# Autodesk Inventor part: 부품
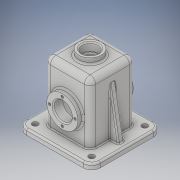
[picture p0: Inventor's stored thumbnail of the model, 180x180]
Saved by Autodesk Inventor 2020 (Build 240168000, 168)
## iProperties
Created: 2022-11
Part Number: 부품
Material: 일반
Document SubType Name: Modeling
Designer: com
Density: 1 g/cm^3
Appearance: 기본값
Author: com
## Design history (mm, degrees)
sketch "스케치1"
  geometry: L1 (65, -62)-(-65, -62); L2 (-65, -62)-(-65, 62); L3 (-65, 62)-(65, 62); L4 (65, 62)-(65, -62); L5 (65, -62)-(-65, 62); L6 (-65, -62)-(65, 62); 1 further point
  constraints: 12 end point, 2 midpoint, 2 parallel, 1 horizontal, 1 perpendicular
  dimensions: "d0" = 130 distance of L1.start L1.end; "d1" = 124 distance of L3.end L1.start
extrude "돌출1" new body sketch "스케치1" distance "d2" = 10; taper "d3" = 0 deg
fillet "모깎기1" dims "d4" = 15
fillet "모깎기2" dims "d5" = 3
sketch "스케치2"
  geometry: L1 (50, -59)-(-50, -59) reference; L2 (62, 47)-(62, -47) reference; L3 (-50, 59)-(50, 59) reference; L4 (-62, -47)-(-62, 47) reference; A1 r 12 centre (-50, -47) between (-62, -47) and (-50, -59) reference; A2 r 12 centre (50, -47) between (50, -59) and (62, -47) reference; A3 r 12 centre (50, 47) between (62, 47) and (50, 59) reference; A4 r 12 centre (-50, 47) between (-50, 59) and (-62, 47) reference; 5 further points
  constraints: 4 coincident
hole "구멍1" sketch "스케치2" at (-50, 47), (-50, -47), (50, -47), (50, 47) diameter "d6" = 10; stored, may be unused: countersink angle "d10" = 90 deg, drill point angle "d12" = 118 deg; dims "d7" = 6, "d8" = 8, "d9" = 4.4, "d11" = 8
sketch "스케치3"
  geometry: L1 (-40, 40)-(40, 40); L2 (40, 40)-(40, -40); L3 (40, -40)-(-40, -40); L4 (-40, -40)-(-40, 40); L5 (-40, 40)-(40, -40); L6 (40, 40)-(-40, -40); 1 further point
  constraints: 12 end point, 2 midpoint, 2 parallel, 1 horizontal, 1 perpendicular
  dimensions: "d13" = 80 distance of L1.start L1.end; "d25" = 80 distance of L1.end L2.end
extrude "돌출2" join sketch "스케치3" distance "d14" = 107; taper "d15" = 0 deg
fillet "모깎기3" dims "d16" = 10
sketch "스케치4"
  geometry: L1 (50, -62)-(-50, -62) reference; L2 (65, 47)-(65, -47) reference; L3 (-50, 62)-(50, 62) reference; L4 (-65, -47)-(-65, 47) reference; L5 (-32, 32)-(32, 32); L6 (32, 32)-(32, -32); L7 (32, -32)-(-32, -32); L8 (-32, -32)-(-32, 32); L9 (-32, 32)-(32, -32); L10 (32, 32)-(-32, -32); C1 r 5 at (50, 47) reference; C2 r 5 at (-50, -47) reference; C3 r 5 at (-50, 47) reference; C4 r 5 at (50, -47) reference; A1 r 15 centre (-50, -47) between (-65, -47) and (-50, -62) reference; A2 r 15 centre (50, -47) between (50, -62) and (65, -47) reference; A3 r 15 centre (50, 47) between (65, 47) and (50, 62) reference; A4 r 15 centre (-50, 47) between (-50, 62) and (-65, 47) reference; 1 further point
  constraints: 12 end point, 2 midpoint, 2 parallel, 1 horizontal, 1 perpendicular
  dimensions: "d17" = 64 distance of L5.start L5.end; "d18" = 64 distance between parallel lines of L5 L7
extrude "돌출3" cut sketch "스케치4" distance "d19" = 99; taper "d20" = 0 deg
sketch "스케치6"
  geometry: L1 (60, 97)-(60, 0) reference; L2 (0, 97)-(60, 97) reference; L3 (0, 0)-(0, 97) reference; L4 (60, 0)-(0, 0) reference; L5 (-20, -10)-(80, -10) reference; C1 r 16 at (30, 45); C2 r 27.5 at (30, 45); 1 further point
  constraints: 2 centre point, 1 coincident
  dimensions: "d30" = 55 distance from line of C1.centre L5; "d31" = 32 diameter of C1; "d32" = 55 diameter of C2
extrude "돌출6" join sketch "스케치6" distance "d33" = 9; taper "d34" = 0 deg
fillet "모깎기4" dims "d35" = 3
sketch "스케치7"
  geometry: L1 (0, 0)-(0, 97) reference; L2 (60, 0)-(0, 0) reference; L3 (60, 97)-(60, 0) reference; L4 (0, 97)-(60, 97) reference; L5 (-20, -10)-(80, -10) reference; C1 r 16 at (30, 45); C2 r 27.5 at (30, 45); 2 further points
  constraints: 2 centre point, 1 coincident, 1 midpoint, 1 vertical alignment
  dimensions: "d36" = 55 distance from line of L5 C1.centre; "d37" = 55 diameter of C2; "d38" = 32 diameter of C1
extrude "돌출7" join sketch "스케치7" distance "d39" = 9; taper "d40" = 0 deg
sketch "스케치8"
  geometry: C1 r 16 at (0, 0) reference; 1 further point
extrude "돌출8" cut sketch "스케치8" extent not by distance; stored distance "d41" = 9; taper "d42" = 0 deg
sketch "스케치9"
  geometry: C1 r 20 at (0, 0); C2 r 14 at (0, 0); 1 further point
  constraints: 2 centre point, 2 coincident
  dimensions: "d43" = 40 diameter of C1; "d44" = 28 diameter of C2
extrude "돌출9" join sketch "스케치9" distance "d45" = 10; taper "d46" = 0 deg
fillet "모깎기5" dims "d47" = 3
sketch "스케치10"
  geometry: C1 r 10.5 at (0, 0); C2 r 14 at (0, 0) reference; C3 r 14 at (0, 0); 1 further point
  constraints: 2 centre point, 2 coincident, 1 concentric
  dimensions: "d48" = 21 diameter of C1
extrude "돌출10" cut sketch "스케치10" distance "d49" = 4; taper "d50" = 0 deg
sketch "스케치11"
  geometry: C1 r 10.5 at (0, 0) reference; C2 r 10.5 at (0, 0); 1 further point
  constraints: 1 centre point, 1 coincident, 1 concentric
extrude "돌출11" cut sketch "스케치11" extent not by distance; stored distance "d51" = 10; taper "d52" = 0 deg
sketch "스케치12"
  geometry: C1 r 27.5 at (0, 0) reference; C2 r 16 at (0, 0) reference; 5 further points
hole "구멍2" sketch "스케치12" at (0, 22.5), (22.5, 0), (0, -22.5), (-22.5, 0) diameter "d55" = 4.3434; stored, may be unused: countersink angle "d59" = 90 deg, drill point angle "d61" = 118 deg; dims "d56" = 10.973, "d57" = 4, "d58" = 2, "d60" = 16.265
sketch "스케치13"
  geometry: C1 r 27.5 at (0, 0) reference; C2 r 16 at (0, 0) reference; 5 further points
hole "구멍3" sketch "스케치13" at (0, 22.5), (22.5, 0), (-22.5, 0), (0, -22.5) diameter "d63" = 4.3434; stored, may be unused: countersink angle "d67" = 90 deg, drill point angle "d69" = 118 deg; dims "d64" = 10.973, "d65" = 4, "d66" = 2, "d68" = 16.265
chamfer "모따기1" distance "d70" = 2; stored, may be unused: second distance "d71" = 2, angle "d72" = 45 deg
chamfer "모따기2" distance "d73" = 2; stored, may be unused: second distance "d74" = 2, angle "d75" = 45 deg
chamfer "모따기3" distance "d76" = 2; stored, may be unused: second distance "d77" = 2, angle "d78" = 45 deg
chamfer "모따기4" distance "d79" = 2; stored, may be unused: second distance "d80" = 2, angle "d81" = 45 deg
sketch "스케치14"
  geometry: L1 (40, 10)-(40, 107) reference; L2 (-40, 107)-(-40, 10) reference; L3 (50, 10)-(-50, 10) reference; L4 (50, 10)-(62, 10) reference; L5 (-62, 10)-(-50, 10) reference; L6 (40, 96.634)-(55.276, 10); L7 (-40, 96.634)-(-55.276, 10); 1 further point
  constraints: 4 end point, 4 point on line, 1 horizontal alignment
  dimensions: "d82" = 100 deg angle of L4 L6; "d83" = 100 deg angle of L5 L7
extrude "돌출12" join sketch "스케치14" stored distance "d86" = 10; taper "d87" = 0 deg
fillet "모깎기6" dims "d88" = 2
node "솔리드1"
node "투영된 루프1"
node "투영된 루프2"
node "투영된 루프4"
node "투영된 루프5"
node "투영된 루프6"
node "투영된 루프7"
node "투영된 루프8"
node "투영된 루프9"
feature "A9D066F2-1C7D-4E18-AEED-F7BC21143FA4" dims "d6" = 10, "d7" = 6, "d8" = 8, "d9" = 4.4, "d10" = 90 deg, "d11" = 8, "d12" = 118 deg
